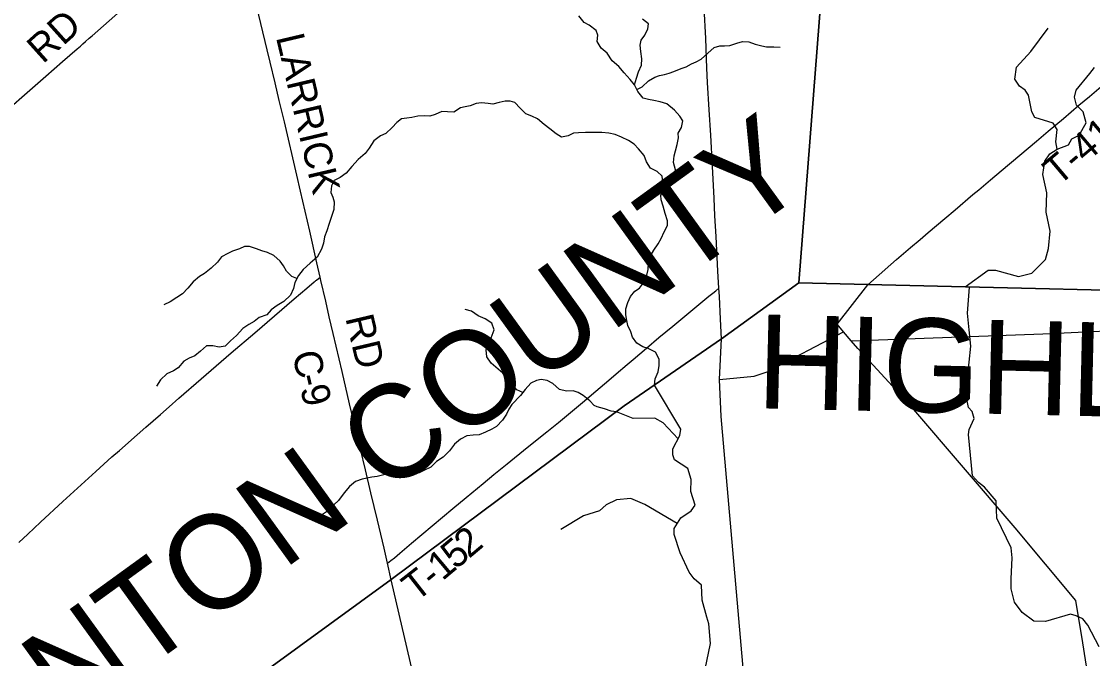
# Model space of a CAD drawing. Extents: x 0 to 34, y 0 to 22.
# Drawn here: x 4.871 to 7.032, y 15.108 to 16.393 of the extents above; entities that cross this region are included whole.
import ezdxf

# ---------------------------------------------------------------- set-up
doc = ezdxf.new("R2010")
doc.units = 0
for name, color, linetype in [('Default', 7, 'Continuous'), ('GM_X_County_Road', 7, 'Continuous'), ('GM_X_County_Road_Text', 7, 'Continuous'), ('GM_X_County_Text', 7, 'Continuous'), ('GM_X_Minor_River', 7, 'Continuous'), ('GM_X_State_Route', 7, 'Continuous'), ('GM_X_Township_Road', 7, 'Continuous'), ('GM_X_Township_Road_Text', 7, 'Continuous'), ('SH_Cut_Line', 7, 'Continuous')]:
    doc.layers.add(name, color=color, linetype=linetype)

msp = doc.modelspace()

# ---------------------------------------------------------------- linework, layer by layer
at = {"layer": 'Default'}
msp.add_lwpolyline([(6.6858, 19.0362), (6.6949, 19.1537), (6.8302, 20.9), (3.1229, 20.9), (2.9275, 20.8467), (2.2946, 20.6707), (2.1, 20.6202), (2.1, 17.1279), (2.1211, 17.1003), (3.2076, 15.5689), (3.4902, 15.1704), (4.0558, 14.3671), (4.1658, 14.2105), (4.302, 14.3105), (5.6165, 15.2674), (6.0871, 15.6176), (6.2834, 15.7529), (6.4392, 15.8657), (6.5428, 17.1931), (6.5451, 17.2211), (6.6309, 18.3364), (6.6363, 18.3979), (6.6654, 18.7733)], dxfattribs=at)
for points in [[(8.9, 15.8067), (8.9, 19.2947), (8.3519, 19.0632), (7.2653, 18.6041), (6.6732, 18.3539), (6.6309, 18.3364), (6.5451, 17.2211), (6.5428, 17.1931), (6.4392, 15.8657), (6.5786, 15.8624), (7.3679, 15.8435), (8.1324, 15.8252)], [(4.022, 14.1), (8.9, 14.1), (8.9, 15.8067), (8.1324, 15.8252), (7.3679, 15.8435), (6.5786, 15.8624), (6.4392, 15.8657), (6.2834, 15.7529), (6.0871, 15.6176), (5.6165, 15.2674), (4.302, 14.3105), (4.1658, 14.2105)]]:
    msp.add_lwpolyline(points, close=True, dxfattribs=at)
at = {"layer": 'GM_X_County_Road'}
for p, q in [((5.6167, 15.2669), (5.6091, 15.3005)), ((5.8876, 14.1), (5.6167, 15.2669))]:
    msp.add_line(p, q, dxfattribs=at)
for points in [[(5.4736, 15.8768), (5.4668, 15.9062), (5.4525, 15.9699), (5.4338, 16.0503), (5.4262, 16.083), (5.4012, 16.1901), (5.3909, 16.2337), (5.3826, 16.2687), (5.3726, 16.3104), (5.3665, 16.3358), (5.3539, 16.389), (5.3368, 16.459), (5.3183, 16.537), (5.305, 16.5939), (5.2998, 16.6151)], [(4.8652, 15.3418), (4.8834, 15.3587), (4.9094, 15.3828), (4.9545, 15.4246), (5.021, 15.4853), (5.0534, 15.5144), (5.0684, 15.5274), (5.1041, 15.5593), (5.1215, 15.5743), (5.151, 15.6), (5.1688, 15.6155), (5.1883, 15.6328), (5.2332, 15.6721), (5.2939, 15.7245), (5.3417, 15.7651), (5.4209, 15.8331), (5.4464, 15.8549), (5.4615, 15.8675), (5.4631, 15.8688), (5.4648, 15.8701), (5.4661, 15.8711), (5.4736, 15.8768)], [(5.6091, 15.3005), (5.6024, 15.3305), (5.5893, 15.3868), (5.576, 15.4424), (5.565, 15.4883), (5.5547, 15.5299), (5.5427, 15.5801), (5.5329, 15.6218), (5.5176, 15.6871), (5.4999, 15.7634), (5.492, 15.7973), (5.4848, 15.8288), (5.475, 15.8705), (5.4736, 15.8768)]]:
    msp.add_lwpolyline(points, dxfattribs=at)
at = {"layer": 'GM_X_Minor_River'}
for points in [[(6.1479, 15.6595), (6.1495, 15.6722), (6.1557, 15.6862), (6.1577, 15.6987), (6.1574, 15.712), (6.1503, 15.7257), (6.1356, 15.733), (6.125, 15.7365), (6.1129, 15.7438), (6.1039, 15.756), (6.1002, 15.7667), (6.0942, 15.7796), (6.0924, 15.7899), (6.0906, 15.8013), (6.0903, 15.8135), (6.0942, 15.8263), (6.1, 15.8384), (6.1084, 15.8486), (6.118, 15.855), (6.1279, 15.8686), (6.1318, 15.8784), (6.1353, 15.8925), (6.1358, 15.9057), (6.1397, 15.9186), (6.1467, 15.9315), (6.1555, 15.9443), (6.162, 15.9549), (6.1678, 15.9685), (6.1744, 15.981), (6.1745, 15.9909), (6.17, 16.0053), (6.166, 16.0205), (6.1615, 16.0331), (6.1608, 16.0426), (6.1701, 16.0573), (6.1823, 16.0709), (6.1908, 16.0807), (6.1905, 16.0936), (6.1868, 16.1081), (6.1881, 16.1221), (6.1908, 16.1316), (6.1943, 16.1445), (6.1967, 16.1581), (6.196, 16.1676), (6.2026, 16.179), (6.2057, 16.1922), (6.1993, 16.2021), (6.1884, 16.214), (6.1733, 16.2266), (6.1597, 16.2309), (6.1468, 16.2333), (6.1358, 16.2353), (6.1252, 16.2384), (6.1143, 16.2514), (6.1079, 16.2647), (6.0993, 16.2758), (6.0873, 16.2891), (6.0763, 16.3017), (6.0631, 16.3132), (6.0526, 16.3289), (6.0406, 16.3388), (6.0327, 16.3526), (6.0336, 16.3651), (6.0302, 16.3746), (6.0163, 16.3853), (6.006, 16.3907), (5.9955, 16.4041)], [(6.1078, 16.2648), (6.1122, 16.2783), (6.1158, 16.2912), (6.1223, 16.3048), (6.1224, 16.3177), (6.1206, 16.3325), (6.1192, 16.3451), (6.1216, 16.3549), (6.1289, 16.3651), (6.1351, 16.3776), (6.1363, 16.3879), (6.1238, 16.3974)], [(6.9608, 16.1349), (6.9579, 16.1497), (6.9608, 16.1747), (6.9526, 16.1874), (6.9156, 16.1991), (6.9097, 16.2106), (6.9032, 16.2444), (6.8961, 16.2543), (6.8845, 16.2624), (6.8751, 16.2765), (6.8788, 16.3004), (6.9076, 16.3324), (6.943, 16.379)], [(6.1124, 16.2554), (6.1231, 16.2612), (6.1361, 16.2728), (6.1487, 16.2807), (6.1582, 16.2837), (6.1681, 16.2855), (6.1776, 16.2885), (6.1872, 16.2918), (6.202, 16.2978), (6.2123, 16.3015), (6.2226, 16.3075), (6.2325, 16.3112), (6.2424, 16.3165), (6.2558, 16.3285), (6.2684, 16.3406), (6.2802, 16.3435), (6.2897, 16.3438), (6.3004, 16.3441), (6.3144, 16.3489), (6.3255, 16.3527), (6.3384, 16.3514), (6.3513, 16.3472), (6.3649, 16.3436), (6.3744, 16.3413), (6.3892, 16.3416), (6.4017, 16.3411)], [(6.7752, 15.8575), (6.8217, 15.8912), (6.8365, 15.8911), (6.8826, 15.8781), (6.9099, 15.885), (6.9375, 15.9124), (6.9435, 15.9351), (6.9465, 15.9696), (6.9386, 16.008), (6.9401, 16.0471), (6.9322, 16.084), (6.9359, 16.1113), (6.9463, 16.126), (6.9608, 16.1349), (6.984, 16.1438), (6.9906, 16.1559), (7.0055, 16.1637), (7.0194, 16.1886), (7.0135, 16.2106), (6.9997, 16.224), (6.996, 16.24), (6.9992, 16.254), (7.0265, 16.2879), (7.0361, 16.2996)], [(6.1725, 16.06), (6.1649, 16.0688), (6.1638, 16.0805), (6.1536, 16.0905), (6.14, 16.0967), (6.1321, 16.11), (6.1273, 16.1226), (6.116, 16.1359), (6.107, 16.1455), (6.0957, 16.1528), (6.0817, 16.1594), (6.0688, 16.1648), (6.0559, 16.1675), (6.0419, 16.1688), (6.0301, 16.1688), (6.0195, 16.1685), (6.0088, 16.1686), (5.9951, 16.168), (5.9845, 16.1673), (5.9742, 16.1624), (5.9605, 16.1591), (5.9496, 16.166), (5.9371, 16.176), (5.9254, 16.1848), (5.9118, 16.1967), (5.9005, 16.2021), (5.8888, 16.2067), (5.8774, 16.2178), (5.8665, 16.2293), (5.8567, 16.232), (5.8468, 16.2321), (5.8346, 16.2295), (5.8221, 16.2258), (5.8126, 16.2274), (5.7993, 16.2286), (5.7883, 16.2276), (5.7761, 16.2224), (5.7662, 16.2205), (5.7567, 16.2183), (5.7433, 16.2101), (5.7304, 16.2102), (5.719, 16.211), (5.7057, 16.2054), (5.6947, 16.2021), (5.6833, 16.2026), (5.6704, 16.2015), (5.6586, 16.1989), (5.6487, 16.1979), (5.6377, 16.1964), (5.6281, 16.1893), (5.6189, 16.1791), (5.6063, 16.1671), (5.5952, 16.1618), (5.5819, 16.1517), (5.5722, 16.1373), (5.5646, 16.1268), (5.55, 16.1143), (5.5374, 16.1), (5.5263, 16.0868), (5.5141, 16.0782), (5.5015, 16.0718), (5.4961, 16.0612), (5.4952, 16.0479), (5.4993, 16.0384), (5.5015, 16.0289), (5.501, 16.0133), (5.4963, 15.9993), (5.492, 15.9853), (5.487, 15.9705), (5.482, 15.9584), (5.4803, 15.9455), (5.4761, 15.9334), (5.4676, 15.9175), (5.453, 15.9051), (5.4389, 15.8927), (5.4297, 15.8802), (5.4224, 15.8666), (5.42, 15.8545), (5.4134, 15.8409), (5.4004, 15.8281), (5.387, 15.8202), (5.3744, 15.8112), (5.3656, 15.8014), (5.3504, 15.7954), (5.3401, 15.7879), (5.3294, 15.7815), (5.3176, 15.7736), (5.3049, 15.7597), (5.2923, 15.7488), (5.2816, 15.7379), (5.2698, 15.7357), (5.2569, 15.7388), (5.244, 15.7389), (5.2321, 15.728), (5.2203, 15.7186), (5.2089, 15.7137), (5.1986, 15.7077), (5.1871, 15.6945), (5.1775, 15.6881), (5.1642, 15.6818), (5.1512, 15.6697)], [(5.4266, 15.8745), (5.4164, 15.8781), (5.4058, 15.8895), (5.3995, 15.8998), (5.3927, 15.9094), (5.3803, 15.9209), (5.3674, 15.9266), (5.356, 15.9301), (5.3447, 15.9344), (5.331, 15.9387), (5.3208, 15.9388), (5.3105, 15.9339), (5.2968, 15.9294), (5.2873, 15.925), (5.2747, 15.9178), (5.2666, 15.9073), (5.2536, 15.8952), (5.2402, 15.8847), (5.2303, 15.8783), (5.2169, 15.8674), (5.2062, 15.8546), (5.1955, 15.8436), (5.184, 15.8358), (5.171, 15.8275), (5.1577, 15.8215)], [(6.7893, 15.6061), (6.782, 15.614), (6.7763, 15.6414), (6.7868, 15.738), (6.7834, 15.7711), (6.7797, 15.8046), (6.7838, 15.8569)], [(5.8825, 15.6443), (5.8706, 15.65), (5.8589, 15.663), (5.8503, 15.6736), (5.8424, 15.6832), (5.8281, 15.6958), (5.8183, 15.7039), (5.81, 15.7165), (5.8086, 15.7305), (5.8113, 15.7411), (5.8187, 15.7547), (5.8245, 15.7706), (5.8197, 15.7843), (5.8064, 15.7932), (5.7924, 15.7993), (5.7788, 15.8082), (5.7663, 15.8117)], [(5.1512, 15.6697), (5.1435, 15.6573)], [(6.0267, 15.618), (6.0174, 15.6276), (6.0046, 15.6383), (5.9944, 15.6445), (5.9841, 15.6476), (5.9705, 15.6473), (5.9568, 15.6508), (5.9432, 15.6627), (5.9319, 15.6685), (5.9194, 15.6709), (5.9099, 15.6686), (5.8984, 15.663), (5.8873, 15.6506), (5.8781, 15.6385), (5.8606, 15.62)], [(6.2505, 15.0866), (6.2612, 15.1381), (6.2576, 15.1781), (6.254, 15.1911), (6.2447, 15.2258), (6.2428, 15.2558), (6.2286, 15.269), (6.2185, 15.2824), (6.1997, 15.3211), (6.1881, 15.3581), (6.188, 15.3703), (6.2012, 15.3917), (6.2224, 15.4055), (6.2305, 15.4175), (6.2215, 15.4446), (6.2222, 15.4689), (6.2157, 15.4914), (6.1886, 15.5086), (6.185, 15.5189), (6.1855, 15.531), (6.1993, 15.5578), (6.2017, 15.5703), (6.1479, 15.6595)], [(5.8606, 15.62), (5.854, 15.6107), (5.8497, 15.6009), (5.8415, 15.5888), (5.8296, 15.5756), (5.82, 15.5704), (5.8074, 15.5645), (5.7944, 15.5589), (5.7822, 15.5583), (5.7697, 15.5573), (5.7566, 15.5502), (5.7444, 15.5405), (5.7343, 15.5269), (5.722, 15.5141), (5.7082, 15.5052), (5.6967, 15.4939), (5.6829, 15.4872), (5.673, 15.4827), (5.6634, 15.4806), (5.6493, 15.48), (5.6387, 15.4793), (5.625, 15.4791), (5.6151, 15.4792), (5.6018, 15.4782), (5.5884, 15.4753), (5.5781, 15.4735), (5.5583, 15.4699), (5.5449, 15.4651), (5.5326, 15.455), (5.5218, 15.4418), (5.5106, 15.4268), (5.501, 15.4177), (5.4902, 15.4065), (5.4784, 15.3986)], [(6.0714, 15.6053), (6.0609, 15.6066), (6.0473, 15.6113), (6.0325, 15.6153), (6.0267, 15.618)], [(6.1957, 15.5509), (6.1654, 15.5834), (6.1492, 15.5924), (6.1055, 15.5919), (6.0714, 15.6053)], [(7.0455, 15.1318), (7.0226, 15.1751), (7.0125, 15.1878), (6.9993, 15.1941), (6.988, 15.1973), (6.9375, 15.1825), (6.9135, 15.1832), (6.8899, 15.2011), (6.875, 15.2218), (6.8678, 15.2485), (6.8681, 15.269), (6.8699, 15.3108), (6.8679, 15.3313), (6.8388, 15.3907), (6.8378, 15.426), (6.8143, 15.4537), (6.8019, 15.4627), (6.7899, 15.4765), (6.7821, 15.5599), (6.783, 15.5697), (6.7933, 15.592), (6.7893, 15.6061)], [(6.1941, 15.3802), (6.1286, 15.4187), (6.1003, 15.4305), (6.0717, 15.4283), (6.051, 15.4176), (6.0375, 15.406), (6.005, 15.3955), (5.9589, 15.3681)]]:
    msp.add_lwpolyline(points, dxfattribs=at)
at = {"layer": 'GM_X_State_Route'}
for points in [[(6.2837, 15.7524), (6.2815, 15.7922), (6.2791, 15.8381), (6.2781, 15.8546), (6.276, 15.889), (6.2724, 15.9591), (6.2702, 16.0007), (6.2684, 16.0367), (6.265, 16.1006), (6.2617, 16.1633), (6.2587, 16.2147), (6.2554, 16.2699), (6.2541, 16.2985), (6.2517, 16.3587), (6.2483, 16.4201)], [(6.6018, 14.1), (6.6072, 14.1303), (6.6089, 14.1641), (6.605, 14.2102), (6.5646, 14.3834), (6.4897, 14.6653), (6.4666, 14.7987), (6.4578, 14.8201), (6.4436, 14.8409), (6.3816, 14.9206), (6.3581, 14.9518), (6.3425, 14.9801), (6.3326, 15.0275), (6.2826, 15.596), (6.2795, 15.671), (6.2837, 15.7524)]]:
    msp.add_lwpolyline(points, dxfattribs=at)
at = {"layer": 'GM_X_Township_Road'}
msp.add_line((6.5453, 15.7486), (6.5297, 15.767), dxfattribs=at)
for points in [[(4.828, 16.202), (4.8986, 16.2638), (4.9202, 16.2825), (4.9538, 16.312), (4.9834, 16.3377), (4.9896, 16.3432), (4.9945, 16.3476), (4.9998, 16.3522), (5.0076, 16.359), (5.0133, 16.364), (5.0937, 16.4343), (5.1264, 16.4629), (5.1929, 16.5209), (5.2208, 16.5457), (5.2452, 16.5669), (5.2722, 16.5908), (5.2877, 16.6042), (5.2998, 16.6151)], [(6.5788, 15.8619), (6.6017, 15.882), (6.6252, 15.9023), (6.6369, 15.9125), (6.6651, 15.9368), (6.6841, 15.9529), (6.7007, 15.967), (6.7339, 15.9951), (6.7551, 16.0132), (6.7906, 16.0435), (6.8025, 16.0534), (6.812, 16.0614), (6.8262, 16.0735), (6.8475, 16.0916), (6.8857, 16.1234), (6.9192, 16.1512), (6.9428, 16.1714), (6.9738, 16.1973), (7.0043, 16.2237), (7.0258, 16.2416), (7.0544, 16.2655)], [(5.6091, 15.3005), (5.6161, 15.3057), (5.6235, 15.3113), (5.634, 15.3201), (5.6576, 15.3403), (5.7415, 15.4104), (5.7682, 15.4327), (5.8023, 15.4607), (5.8243, 15.4789), (5.8506, 15.5007), (5.8913, 15.5334), (5.9309, 15.5654), (5.9542, 15.584), (6.003, 15.6243), (6.0301, 15.6471), (6.056, 15.6693), (6.0706, 15.6818), (6.0928, 15.7007), (6.1052, 15.7111), (6.1319, 15.7342), (6.1573, 15.7552), (6.1852, 15.778), (6.242, 15.8254), (6.2577, 15.8385), (6.266, 15.8451), (6.2719, 15.8497), (6.2781, 15.8546)], [(6.5297, 15.767), (6.5167, 15.7822), (6.5788, 15.8619)], [(6.2795, 15.671), (6.3495, 15.6776), (6.3758, 15.6859), (6.5297, 15.767)], [(6.5453, 15.7486), (6.9318, 15.7625), (7.1599, 15.7735), (7.1747, 15.774), (7.1884, 15.7718), (7.2556, 15.692), (7.3321, 15.5994), (7.3588, 15.5787)], [(7.2512, 14.1), (7.1325, 14.605), (7.1181, 14.6116), (7.1099, 14.6333), (7.0235, 15.0709), (7.0125, 15.1398), (6.9982, 15.225), (6.8762, 15.3717), (6.6676, 15.6148), (6.5583, 15.7333), (6.5453, 15.7486)]]:
    msp.add_lwpolyline(points, dxfattribs=at)
at = {"layer": 'SH_Cut_Line'}
for points in [[(6.6858, 19.0362), (6.6949, 19.1537), (6.8302, 20.9), (2.1, 20.9), (2.1, 14.1), (4.022, 14.1), (4.1658, 14.2105), (4.302, 14.3105), (5.6165, 15.2674), (6.0871, 15.6176), (6.2834, 15.7529), (6.4392, 15.8657), (6.5428, 17.1931), (6.5451, 17.2211), (6.6309, 18.3364), (6.6363, 18.3979), (6.6654, 18.7733)], [(6.6654, 18.7733), (6.6363, 18.3979), (6.6309, 18.3364), (6.5451, 17.2211), (6.5428, 17.1931), (6.4392, 15.8657), (6.5786, 15.8624), (7.3679, 15.8435), (8.1324, 15.8252), (8.9, 15.8067), (8.9, 20.9), (6.8302, 20.9), (6.6949, 19.1537), (6.6858, 19.0362)]]:
    msp.add_lwpolyline(points, dxfattribs=at)

# ---------------------------------------------------------------- texts
at = {"layer": 'GM_X_County_Road_Text'}
for s, height, rotation, p in [('LARRICK', 0.05682, 283.2842, (5.384, 16.3612)), ('RD', 0.05682, 283.3269, (5.524, 15.7949)), ('C', 0.0568, 282.8472, (5.4167, 15.7226)), ('-', 0.0568, 283.0722, (5.4271, 15.6769)), ('9', 0.0568, 284.1821, (5.4327, 15.653))]:
    msp.add_text(s, height=height, rotation=rotation, dxfattribs=at).set_placement(p)
at = {"layer": 'GM_X_County_Text'}
for s, rotation, p in [('CLINTON COUNTY', 35.9139, (4.6459, 14.7404)), ('HIGHLAND COUNTY', 358.6406, (6.3531, 15.6128))]:
    msp.add_text(s, height=0.189394, rotation=rotation, dxfattribs=at).set_placement(p)
at = {"layer": 'GM_X_Township_Road_Text'}
for s, height, rotation, p in [('RD', 0.05682, 41.9127, (4.9139, 16.306)), ('T-41', 0.05682, 40.2581, (6.9634, 16.0596)), ('2', 0.0568, 40.1203, (5.7739, 15.3085)), ('5', 0.0568, 40.0984, (5.7471, 15.286)), ('1', 0.0568, 39.9829, (5.7202, 15.2634)), ('T', 0.0568, 38.1257, (5.6672, 15.221)), ('-', 0.0568, 39.702, (5.702, 15.2483))]:
    msp.add_text(s, height=height, rotation=rotation, dxfattribs=at).set_placement(p)

doc.saveas('drawing.dxf')
